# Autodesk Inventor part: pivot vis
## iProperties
Shininess: 64.0
Length Units: 11269
Angle Units: 11279
Time Units: 11290
Mass Units: 11283
Length Display Precision: 3
Angle Display Precision: 2
Compacted: True
Part Number: pivot vis
Document SubType Name: Modeling
Created: 2005-02
Material: Par défaut
Designer: LEGERET Philippe
Density: 0.0
Volumn: 0.0
Area: 0.0
PropertySet Name: Model Information
Control State: 0
Master: False
Checked Out: False
Author: LEGERET Philippe
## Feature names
1. Révolution1 [Revolution]
2. Chanfrein1 [Chamfer]
3. Perçage1 [Hole]
4. Réseau circulaire1 [Circular Pattern]
5. Extrusion1
